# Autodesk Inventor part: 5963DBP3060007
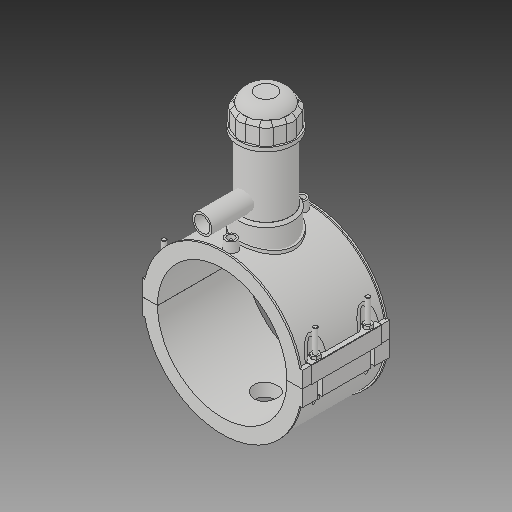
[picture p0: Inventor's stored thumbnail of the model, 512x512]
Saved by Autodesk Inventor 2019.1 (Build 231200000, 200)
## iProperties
Created: 2017-07
Part Number: 5963DBP3060007
Material: Generic
Description: PLASSON TAPPING SADDLE 6''DIPS x 3/4''IPS
Document SubType Name: Modeling
Designer: KIM
Density: 1 g/cm^3
Appearance: Default
Author: KIM
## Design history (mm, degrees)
derived "5963DBP_5963BUP.ipt"
feature "Solid1::5963DBP_5963BUP.ipt"
feature "Solid2::5963DBP_5963BUP.ipt"
feature "Solid3::5963DBP_5963BUP.ipt"
tag "TaggingFeature1"
body "Solid1"
body "Solid2"
body "Solid3"
other parameters: "d0" = 174.5, "d2" = 215.9, "d3" = 43.625, "d4" = 118.11, "d5" = 0, "d6" = 0.1, "d8" = 0, "d19" = 6, "d20" = 6, "d21" = 70.866, "d23" = 0, "d24" = 35.433, "d26" = 0, "d27" = 3, "d28" = 3, "d29" = 3, "d30" = 58.16667, "d31" = 6, "d32" = 0, "d33" = 0, "d34" = 0.6, "d40" = 108.888, "d41" = 75.035, "d43" = 0, "d45" = 0, "d47" = 175.566, "d70" = 15, "d72" = 0, "d73" = 6, "d75" = 5, "d76" = 0, "d77" = 8.725, "d78" = 117.25, "d79" = 15, "d80" = 47.244, "d82" = 5 deg, "d84" = 4, "d85" = 14, "d86" = 0, "d87" = 3, "d88" = 0, "d89" = 1, "d90" = 1, "d91" = 94.488, "d92" = 0, "d93" = 0.5, "d94" = 91.84211, "d96" = 213.588, "d97" = 2.3622, "d98" = 0, "d120" = 140 deg, "d121" = 24.228, "d122" = 20 deg, "d123" = 418.8, "d124" = 125.64, "d126" = 0, "d143" = 179.735, "d145" = 26.84615, "d149" = 2.6175, "d150" = 29.53077, "d153" = 118.11, "d154" = 0, "d156" = 104.7, "d157" = 160 deg, "d159" = 6.98, "d161" = 2.6175, "d162" = 70.866, "d163" = 0, "d164" = 87.25, "d167" = 17.45, "d168" = 102.14634, "d170" = 3.4335, "d172" = 0, "d173" = 1, "d175" = 87.25, "d176" = 20 deg, "d177" = 12.215, "d178" = 34.9, "d180" = 0, "d183" = 13.96, "d184" = 9.772, "d185" = 38.38575, "d186" = 38.38575, "d187" = 104.7, "d188" = 10.47, "d189" = 12.215, "d190" = 0, "d191" = 157.05, "d193" = 7.3248, "d194" = 4.13385, "d195" = 90 deg, "d197" = 0, "d199" = 0, "d200" = 17.45, "d202" = 0, "d203" = 177.038, "d204" = 71.28325, "d205" = 52.5245, "d206" = 63.77975, "d207" = 132.7785, "d208" = 138.08964, "d209" = 164.64534, "d210" = 64.5301, "d211" = 75.035, "d212" = 60.028, "d213" = 46.5516, "d216" = 0, "d217" = 17.45, "d218" = 17.45, "d219" = 3.49, "d222" = 174.5, "d224" = 0, "d225" = 65.024, "d226" = 26.6, "d227" = 21.28, "d228" = 86.106, "d230" = 5.235, "d_" = 174.5, "B_" = 215.9, "L_" = 118.11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
